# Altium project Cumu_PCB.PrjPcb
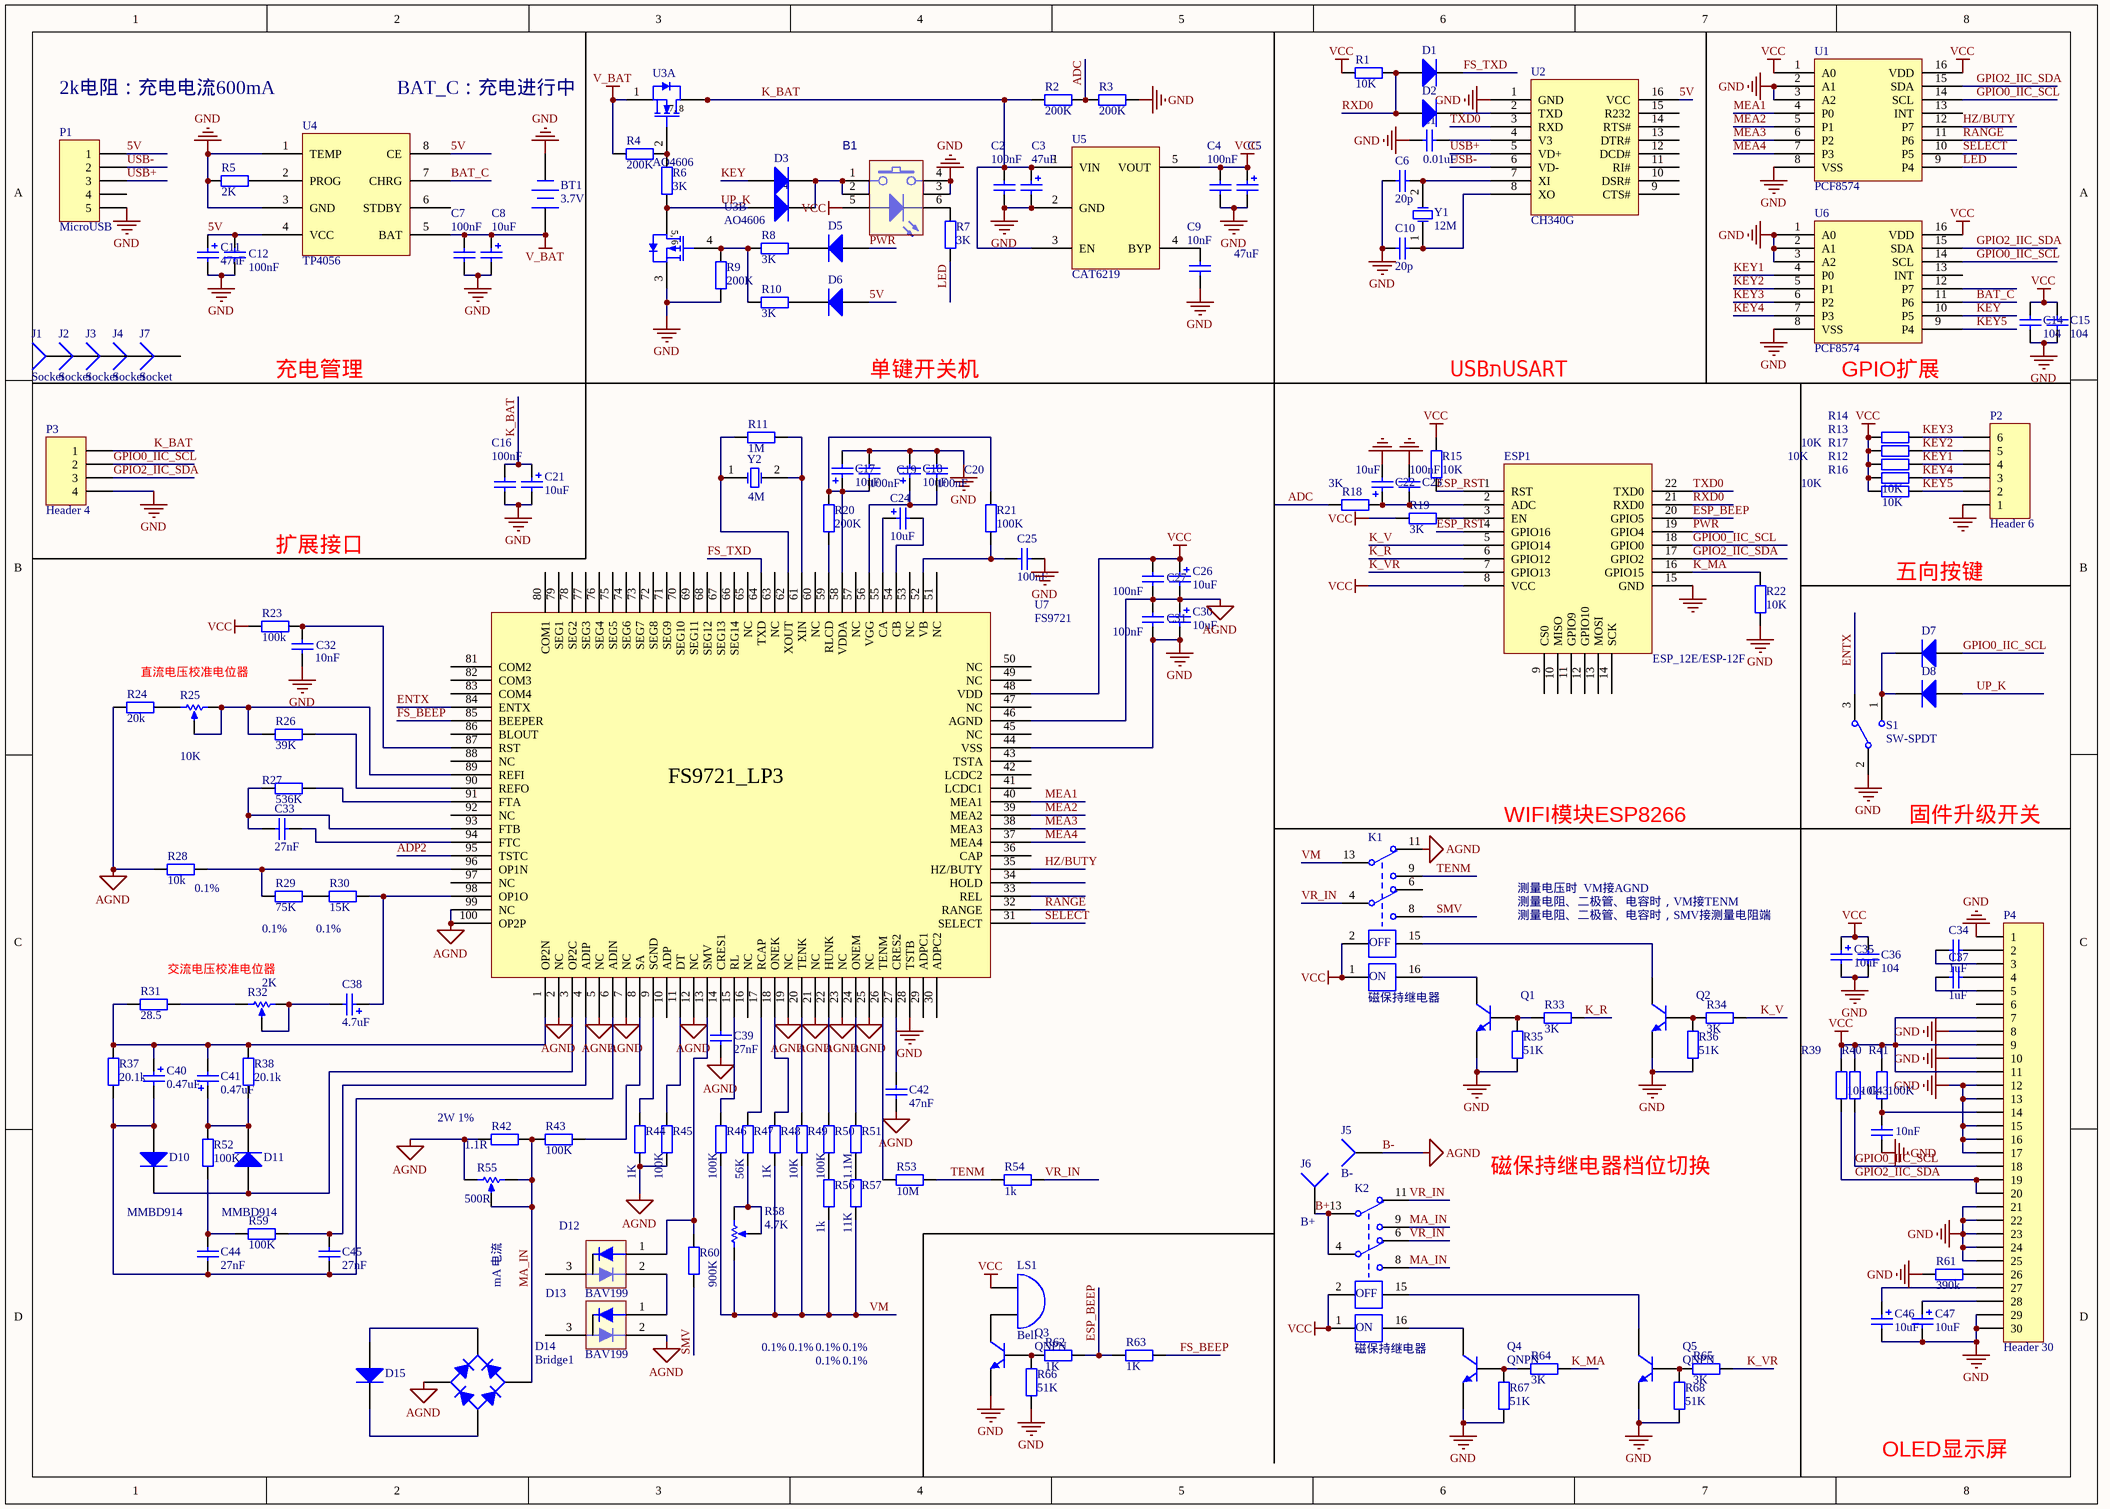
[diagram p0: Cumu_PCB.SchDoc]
1 sheet, 158 parts. Net scope: global (net labels, ports and power ports of the same name join across sheets).
Board file: Cumu_PCB.PcbDoc

## Sheet Cumu_PCB.SchDoc
size A3

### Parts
B1  SW-led  [SW-6-LED]  (value not drawn)
BT1  3.7V  [BAT-2]
C1  value 0.01uF  [0603C]  (hidden comment: Cap)
C2  value 100nF  [0603C]  (hidden comment: Cap)
C3  value 47uF  [SMD-EC-F5]  (hidden comment: Cap Pol2)
C4  value 100nF  [0603C]  (hidden comment: Cap)
C5  value 47uF  [SMD-EC-F5]  (hidden comment: Cap Pol2)
C6  value 20p  [0603C]  (hidden comment: Cap)
C7  value 100nF  [0603C]  (hidden comment: Cap)
C8  value 10uF  [CAP_A]  (hidden comment: Cap Pol2)
C9  value 10nF  [0603C]  (hidden comment: Cap)
C10  value 20p  [0603C]  (hidden comment: Cap)
C11  value 47uF  [SMD-EC-F5]  (hidden comment: Cap Pol2)
C12  value 100nF  [0603C]  (hidden comment: Cap)
C14  value 104  [0603C]  (hidden comment: Cap)
C15  value 104  [0603C]  (hidden comment: Cap)
C16  value 100nF  [0603C]  (hidden comment: Cap)
C17  value 10uF  [CAP_A]  (hidden comment: Cap Pol2)
C18  value 10uF  [CAP_A]  (hidden comment: Cap Pol2)
C19  value 100nF  [0603C]  (hidden comment: Cap)
C20  value 100nF  [0603C]  (hidden comment: Cap)
C21  value 10uF  [CAP_A]  (hidden comment: Cap Pol2)
C22  value 10uF  [CAP_A]  (hidden comment: Cap Pol2)
C23  value 100nF  [0603C]  (hidden comment: Cap)
C24  value 10uF  [CAP_A]  (hidden comment: Cap Pol2)
C25  value 100nF  [0603C]  (hidden comment: Cap)
C26  value 10uF  [CAP_A]  (hidden comment: Cap Pol2)
C27  value 100nF  [0603C]  (hidden comment: Cap)
C30  value 10uF  [CAP_A]  (hidden comment: Cap Pol2)
C31  value 100nF  [0603C]  (hidden comment: Cap)
C32  value 10nF  [0603C]  (hidden comment: Cap)
C33  value 27nF  [0603C]  (hidden comment: Cap)
C34  value 1uF  [0603C]  (hidden comment: Cap)
C35  value 10uF  [CAP_A]  (hidden comment: Cap Pol2)
C36  value 104  [0603C]  (hidden comment: Cap)
C37  value 1uF  [0603C]  (hidden comment: Cap)
C38  value 4.7uF  [CAP_A]  (hidden comment: Cap Pol2)
C39  value 27nF  [0603C]  (hidden comment: Cap)
C40  value 0.47uF  [CAP_A]  (hidden comment: Cap Pol2)
C41  value 0.47uF  [CAP_A]  (hidden comment: Cap Pol2)
C42  value 47nF  [0603C]  (hidden comment: Cap)
C43  value 10nF  [0603C]  (hidden comment: Cap)
C44  value 27nF  [0603C]  (hidden comment: Cap)
C45  value 27nF  [0603C]  (hidden comment: Cap)
C46  value 10uF  [CAP_A]  (hidden comment: Cap Pol2)
C47  value 10uF  [CAP_A]  (hidden comment: Cap Pol2)
D1  MBRA340  [M7 1206]  (value not drawn)
D2  MBRA340  [M7 1206]  (value not drawn)
D3  MBRA340  [M7 1206]  (value not drawn)
D4  MBRA340  [M7 1206]  (value not drawn)
D5  MBRA340  [M7 1206]  (value not drawn)
D6  MBRA340  [M7 1206]  (value not drawn)
D7  MBRA340  [M7 1206]  (value not drawn)
D8  MBRA340  [M7 1206]  (value not drawn)
D10  MMBD914  [SOT-23B]
D11  MMBD914  [SOT-23B]
D12  BAV199  [SOT-23B]
D13  BAV199  [SOT-23B]
D14  Bridge1  [DB107S]
D15  MBRA340  [SMA]  (value not drawn)
ESP1  ESP_12E/ESP-12F  [ESP12_BOT]
J1  Socket  [GDK]
J2  Socket  [GDK]
J3  Socket  [GDK]
J4  Socket  [GDK]
J5  B-  [pen]
J6  B+  [pen]
J7  Socket  [GDK]
K1  磁保持继电器  [HFD2/005-M-L2]
K2  磁保持继电器  [HFD2/005-M-L2]
LS1  Bell  [BUZZ]
P1  MicroUSB  [USB_MICRO -72/66]
P2  Header 6  [5xiang-10*10]
P3  Header 4  [USB_tie]
P4  Header 30  [0,96OLED]
Q1  QNPN  [SOT-23B]  (value not drawn)
Q2  QNPN  [SOT-23B]  (value not drawn)
Q3  QNPN  [SOT-23B]
Q4  QNPN  [SOT-23B]
Q5  QNPN  [SOT-23B]
R1  value 10K  [0603R]  (hidden comment: Res2)
R2  value 200K  [0603R]  (hidden comment: Res2)
R3  value 200K  [0603R]  (hidden comment: Res2)
R4  value 200K  [0603R]  (hidden comment: Res2)
R5  value 2K  [0603R]  (hidden comment: Res2)
R6  value 3K  [0603R]  (hidden comment: Res2)
R7  value 3K  [0603R]  (hidden comment: Res2)
R8  value 3K  [0603R]  (hidden comment: Res2)
R9  value 200K  [0603R]  (hidden comment: Res2)
R10  value 3K  [0603R]  (hidden comment: Res2)
R11  value 1M  [0603R]  (hidden comment: Res2)
R12  value 10K  [0603R]  (hidden comment: Res2)
R13  value 10K  [0603R]  (hidden comment: Res2)
R14  value 10K  [0603R]  (hidden comment: Res2)
R15  value 10K  [0603R]  (hidden comment: Res2)
R16  value 10K  [0603R]  (hidden comment: Res2)
R17  value 10K  [0603R]  (hidden comment: Res2)
R18  value 3K  [0603R]  (hidden comment: Res2)
R19  value 3K  [0603R]  (hidden comment: Res2)
R20  value 200K  [0603R]  (hidden comment: Res2)
R21  value 100K  [0603R]  (hidden comment: Res2)
R22  value 10K  [0603R]  (hidden comment: Res2)
R23  value 100k  [0603R]  (hidden comment: Res2)
R24  value 20k  [0603R]  (hidden comment: Res2)
R25  value 10K  [R3*3]  (hidden comment: RPot)
R26  value 39K  [0603R]  (hidden comment: Res2)
R27  value 536K  [0603R]  (hidden comment: Res2)
R28  value 10k  PackageReference: 0.1%  [0603R]  (hidden comment: Res2)
R29  value 75K  PackageReference: 0.1%  [0603R]  (hidden comment: Res2)
R30  value 15K  PackageReference: 0.1%  [0603R]  (hidden comment: Res2)
R31  value 28.5  [0603R]  (hidden comment: Res2)
R32  value 2K  [R3*3]  (hidden comment: RPot)
R33  value 3K  [0603R]  (hidden comment: Res2)
R34  value 3K  [0603R]  (hidden comment: Res2)
R35  value 51K  [0603R]  (hidden comment: Res2)
R36  value 51K  [0603R]  (hidden comment: Res2)
R37  value 20.1k  [0603R]  (hidden comment: Res2)
R38  value 20.1k  [0603R]  (hidden comment: Res2)
R39  value 10k  [0603R]  (hidden comment: Res2)
R40  value 10k  [0603R]  (hidden comment: Res2)
R41  value 100K  [0603R]  (hidden comment: Res2)
R42  2W 1%  value 1.1R  [AXIAL-0.7]
R43  value 100K  [0603R]  (hidden comment: Res2)
R44  value 1K  [0603R]  (hidden comment: Res2)
R45  value 100K  [0603R]  (hidden comment: Res2)
R46  value 100K  [0603R]  (hidden comment: Res2)
R47  value 56K  [0603R]  (hidden comment: Res2)
R48  value 1K  PackageReference: 0.1%  [0603R]  (hidden comment: Res2)
R49  value 10K  PackageReference: 0.1%  [0603R]  (hidden comment: Res2)
R50  value 100K  PackageReference: 0.1%  [0603R]  (hidden comment: Res2)
R51  value 1.1M  PackageReference: 0.1%  [0603R]  (hidden comment: Res2)
R52  value 100K  [0603R]  (hidden comment: Res2)
R53  value 10M  [0603R]  (hidden comment: Res2)
R54  value 1k  [0603R]
R55  value 500R  [R3*3]  (hidden comment: RPot)
R56  value 1k  PackageReference: 0.1%  [0603R]  (hidden comment: Res2)
R57  value 11K  PackageReference: 0.1%  [0603R]  (hidden comment: Res2)
R58  value 4.7K  [R3*3]  (hidden comment: RPot)
R59  value 100K  [0603R]  (hidden comment: Res2)
R60  value 900K  [0603R]  (hidden comment: Res2)
R61  value 390k  [0603R]  (hidden comment: Res2)
R62  value 1K  [0603R]  (hidden comment: Res2)
R63  value 1K  [0603R]  (hidden comment: Res2)
R64  value 3K  [0603R]  (hidden comment: Res2)
R65  value 3K  [0603R]  (hidden comment: Res2)
R66  value 51K  [0603R]  (hidden comment: Res2)
R67  value 51K  [0603R]  (hidden comment: Res2)
R68  value 51K  [0603R]  (hidden comment: Res2)
S1  SW-SPDT  [SS-12D07]
U1  PCF8574  [SOP-16]
U2  CH340G  [SO-16]
U3  AO4606  [SO-8]  (parts A,B of 2)
U4  TP4056  [SO-8 - 9]
U5  CAT6219  [MA05B]
U6  PCF8574  [SOP-16]
U7  FS9721  [QFP100]
Y1  12M  [HC-49]
Y2  4M  [HC-49]

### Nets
B-: C26.2 C27.1 C30.1 C31.2 C39.2 C42.2 D13.2 D14.4(C) J5.1 K1.11 R24.2 R28.2 R42.2 R44.2 R45.2 R55.1(TOP) U7.2(NC) U7.5(NC) U7.7(NC) U7.12(NC) U7.19(NC) U7.21(NC) U7.23(NC) U7.25(NC) U7.46(AGND) U7.99(NC) U7.100(OP2P)  [also labelled AGND]
GND: B1.3 B1.4 BT1.2(-) C1.2 C2.1 C3.2 C4.1 C5.2 C6.2 C7.1 C8.2 C9.1 C10.2 C11.2 C12.1 C14.2 C15.2 C16.1 C17.2 C18.2 C19.1 C20.1 C21.2 C22.2 C23.1 C25.1 C30.2 C31.1 C32.1 C35.2 C36.2 C43.1 C46.2 C47.2 ESP1.15(GND) P1.5 P2.1 P3.4 P4.1 P4.8 P4.10 P4.12 P4.13 P4.15 P4.16 P4.17 P4.21 P4.22 P4.23 P4.24 P4.25 P4.29 P4.30 Q1.2(E) Q2.2(E) Q3.2(E) Q4.2(E) Q5.2(E) R3.1 R5.1 R9.1 R22.1 R35.1 R36.1 R61.2 R66.1 R67.1 R68.1 S1.2 U1.2(A1) U1.3(A2) U1.8(VSS) U2.1(GND) U3.3(S) U4.1(TEMP) U4.3(GND) U5.2(GND) U6.1(A0) U6.2(A1) U6.3(A2) U6.8(VSS) U7.28(TSTB) U7.44(VSS)
V_BAT: BT1.1(+) C7.2 C8.1 R4.1 U3.1(S) U4.5(BAT)
VCC: B1.5 C4.2 C5.1 C14.1 C15.1 C26.1 C27.2 C35.1 C36.1 ESP1.8(VCC) K1.1(+) K1.2 K2.1(+) K2.2 LS1.2(B) P4.7 P4.9 P4.11 R1.2 R12.2 R13.1 R14.2 R15.2 R16.2 R17.2 R19.1 R23.2 R39.2 R40.2 R41.1 U1.1(A0) U1.16(VDD) U5.5(VOUT) U6.16(VDD) U7.48(VDD)
5V: C11.1 C12.2 D6.1(A) P1.1 U2.16(VCC) U4.4(VCC) U4.8(CE)
ADC: R2.1 R3.2 R18.1
ADP2: U7.95(TSTC)
B+: J6.1 K2.4 K2.13
BAT_C: U4.7(CHRG) U6.11(P6)
ENTX: S1.3 U7.84(ENTX)
ESP_BEEP: ESP1.20(GPIO5) R62.2 R63.1
ESP_RST: ESP1.1(RST) ESP1.4(GPIO16) R15.1
FS_BEEP: R63.2 U7.85(BEEPER)
FS_TXD: D1.2(K) U7.64(TXD)
GPIO0_IIC_SCL: D7.1(A) ESP1.18(GPIO0) P3.2 P4.18 R40.1 U1.14(SCL) U6.14(SCL)
GPIO2_IIC_SDA: ESP1.17(GPIO2) P3.3 P4.19 P4.20 R39.1 U1.15(SDA) U6.15(SDA)
HZ/BUTY: U1.12(P7) U7.35(HZ/BUTY)
K_BAT: C2.2 C3.1 C16.2 C21.1 P3.1 R2.2 U3.7(D) U3.8(D) U5.1(VIN) U5.3(EN)
K_MA: ESP1.16(GPIO15) R22.2 R64.2
K_R: ESP1.6(GPIO12) R33.2
K_V: ESP1.5(GPIO14) R34.2
K_VR: ESP1.7(GPIO13) R65.2
KEY: D3.1(A) U6.10(P5)
KEY1: P2.4 R12.1 U6.4(P0)
KEY2: P2.5 R13.2 U6.5(P1)
KEY3: P2.6 R14.1 U6.6(P2)
KEY4: P2.3 R16.1 U6.7(P3)
KEY5: P2.2 R17.1 U6.9(P4)
LED: R7.2 U1.9(P4)
MA_IN: D14.2(C) K2.8 K2.9 R42.1 R43.2 R55.2(BOT) R55.3(TAP)
MEA1: U1.4(P0) U7.40(MEA1)
MEA2: U1.5(P1) U7.39(MEA2)
MEA3: U1.6(P2) U7.38(MEA3)
MEA4: U1.7(P3) U7.37(MEA4)
PWR: D5.1(A) ESP1.19(GPIO4)
RANGE: U1.11(P6) U7.32(RANGE)
RXD0: D1.1(A) D2.1(A) ESP1.21(RXD0) R1.1
SELECT: U1.10(P5) U7.31(SELECT)
SMV: K1.8 R60.2
TENM: K1.9 R53.2 R54.1
TXD0: ESP1.22(TXD0) U2.3(RXD)
UP_K: D4.1(A) D8.1(A) R6.1 U3.5(D) U3.6(D)
USB+: P1.3 U2.5(VD+)
USB-: P1.2 U2.6(VD-)
VM: K1.13 R46.2 R48.2 R49.2 R56.2 R57.2 R58.1(TOP)
VR_IN: K1.4 K2.6 K2.11 R54.2
NetB1_1: B1.1 B1.2 D3.2(K) D4.2(K)
NetB1_6: B1.6 R7.1
NetC1_1: C1.1 U2.4(V3)
NetC6_1: C6.1 U2.7(XI) Y1.2(OSC2)
NetC9_2: C9.2 U5.4(BYP)
NetC10_1: C10.1 U2.8(XO) Y1.1(OSC1)
NetC17_1: C17.1 C19.2 R20.1 R21.1 U7.58(VDDA)
NetC18_1: C18.1 C20.2 U7.56(VGG)
NetC22_1: C22.1 C23.2 ESP1.2(ADC) R18.2
NetC24_1: C24.1 U7.55(CA)
NetC24_2: C24.2 U7.54(CB)
NetC25_2: C25.2 R21.2 U7.52(VB)
NetC32_2: C32.2 R23.1 U7.87(RST)
NetC33_1: C33.1 U7.94(FTC)
NetC33_2: C33.2 R27.2 U7.93(FTB)
NetC34_1: C34.1 P4.3
NetC34_2: C34.2 P4.2
NetC37_1: C37.1 P4.5
NetC37_2: C37.2 P4.4
NetC38_1: C38.1 R30.1 U7.98(OP1O)
NetC38_2: C38.2 R32.2(BOT) R32.3(TAP)
NetC39_1: C39.1 U7.14(CRES1)
NetC40_1: C40.1 C41.2 R31.2 R37.1 R38.1 U7.1(OP2N)
NetC40_2: C40.2 C44.2 C45.2 D10.1(A) R37.2 U7.6(ADIN)
NetC41_1: C41.1 D11.2(K) R38.2 R52.1
NetC42_1: C42.1 U7.27(CRES2)
NetC43_2: C43.2 P4.14 R41.2
NetC44_1: C44.1 R52.2 R59.1
NetC45_1: C45.1 R59.2 U7.4(ADIP)
NetC46_1: C46.1 P4.27
NetC47_1: C47.1 P4.28
NetD2_2: D2.2(K) U2.2(TXD)
NetD5_2: D5.2(K) R8.1
NetD6_2: D6.2(K) R10.1
NetD7_2: D7.2(K) D8.2(K) S1.1
NetD10_2: D10.2(K) D11.1(A) U7.3(OP2C)
NetD12_1: D12.1 R60.1 U7.13(SMV)
NetD12_2: D12.2 D13.1
NetD14_1: D14.1(K) D15.1(A)
NetD14_3: D14.3(A) D15.2(K)
NetESP1_3: ESP1.3(EN) R19.2
NetK1_15: K1.15 Q2.3(C)
NetK1_16: K1.16 Q1.3(C)
NetK2_15: K2.15 Q5.3(C)
NetK2_16: K2.16 Q4.3(C)
NetLS1_1: LS1.1(A) Q3.3(C)
NetP4_26: P4.26 R61.1
NetQ1_1: Q1.1(B) R33.1 R35.2
NetQ2_1: Q2.1(B) R34.1 R36.2
NetQ3_1: Q3.1(B) R62.1 R66.2
NetQ4_1: Q4.1(B) R64.1 R67.2
NetQ5_1: Q5.1(B) R65.1 R68.2
NetR4_2: R4.2 R6.2 U3.2(G)
NetR5_2: R5.2 U4.2(PROG)
NetR8_2: R8.2 R9.2 R10.2 U3.4(G)
NetR11_1: R11.1 U7.61(XIN) Y2.2(OSC2)
NetR11_2: R11.2 U7.62(XOUT) Y2.1(OSC1)
NetR20_2: R20.2 U7.59(RLCD)
NetR24_1: R24.1 R25.1(TOP)
NetR25_2: R25.2(BOT) R25.3(TAP) R26.2 U7.89(REFI)
NetR26_1: R26.1 U7.90(REFO)
NetR27_1: R27.1 U7.91(FTA)
NetR28_1: R28.1 R29.2 U7.96(OP1N)
NetR29_1: R29.1 R30.2
NetR31_1: R31.1 R32.1(TOP)
NetR43_1: R43.1 U7.8(SA)
NetR44_1: R44.1 U7.9(SGND)
NetR45_1: R45.1 U7.11(DT)
NetR46_1: R46.1 U7.15(RL)
NetR47_1: R47.1 U7.17(RCAP)
NetR47_2: R47.2 R58.2(BOT) R58.3(TAP)
NetR48_1: R48.1 U7.18(ONEK)
NetR49_1: R49.1 U7.20(TENK)
NetR50_1: R50.1 U7.22(HUNK)
NetR50_2: R50.2 R56.1
NetR51_1: R51.1 U7.24(ONEM)
NetR51_2: R51.2 R57.1
NetR53_1: R53.1 U7.26(TENM)

Not connected (* = marked no-connect by the designer): D12 3; D13 3; ESP1 9(CS0) 10(MISO) 11(GPIO9) 12(GPIO10) 13(MOSI) 14(SCK); J1 1; J2 1; J3 1; J4 1; J7 1; K1 6; P1 4; P4 6; U1 13(INT); U2 9(CTS#) 10(DSR#) 11(RI#) 12(DCD#) 13(DTR#) 14(RTS#) 15(R232); U4 6(STDBY); U6 12(P7) 13(INT); U7 10(ADP) 16(NC) 29(ADPC1) 30(ADPC2) 33(REL) 34(HOLD) 36(CAP) 41(LCDC1) 42(LCDC2) 43(TSTA) 45(NC) 47(NC) 49(NC) 50(NC) 51(NC) 53(NC) 57(NC) 60(NC) 63(NC) 65(NC) 66(SEG14) 67(SEG13) 68(SEG12) 69(SEG11) 70(SEG10) 71(SEG9) 72(SEG8) 73(SEG7) 74(SEG6) 75(SEG5) 76(SEG4) 77(SEG3) 78(SEG2) 79(SEG1) 80(COM1) 81(COM2) 82(COM3) 83(COM4) 86(BLOUT) 88(NC) 92(NC) 97(NC)

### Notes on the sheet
- 2k电阻：充电电流600mA
- BAT_C：充电进行中
- 充电管理
- 单键开关机
- USBתUSART
- (near U6) GPIO扩展
- 扩展接口
- 五向按键
- 直流电压校准电位器
- WIFI模块ESP8266
- 固件升级开关
- 测量电压时  VM接AGND
- 测量电阻、二极管、电容时，VM接TENM
- 测量电阻、二极管、电容时，SMV接测量电阻端
- 交流电压校准电位器
- 磁保持继电器档位切换
- mA 电流
- OLED显示屏

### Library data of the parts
B1 = SW-led: Manuf_Part_1: TD-0341; Ref St: ********; cap_dec: ---; Description: Non-Open Push-Button 0.1A 24V
BT1 = Battery: Multicell Battery
C1 C2 C4 C6 C7 C9 C10 C12 C14-C16 C19 C20 C23 C25 C27 C31-C34 C36 C37 C39 C42-C45 = Cap: Capacitor
C3 C5 C8 C11 C17 C18 C21 C22 C24 C26 C30 C35 C38 C40 C41 C46 C47 = Cap Pol2: Polarized Capacitor (Axial)
D1-D8 D15 = Diode 1N5408: 3 Amp Medium Power Silicon Rectifier Diode
D10 D11 = Diode 1N5408: 3 Amp Medium Power Silicon Rectifier Diode; pin to pad: 2>3
D14 = Bridge1: Full Wave Diode Bridge
ESP1 = ESP_12
J5 J6 = Socket
K1 K2 = HFD2/005-M-L2
LS1 = Bell: Electrical Bell
P1 = Header 5: Header, 5-Pin
P2 = Header 6: Header, 6-Pin
P3 = Header 4: Header, 4-Pin
P4 = Header 30: Header, 30-Pin
Q1-Q5 = QNPN: NPN Bipolar Transistor
R1-R24 R26-R31 R33-R54 R56 R57 R59-R68 = Res2: Resistor
R25 R32 R55 R58 = RPot: Potentiometer; Sim Note: Enter the Resistance value and the set point into parameter fields.; Set Position: 0.5
S1 = SW-SPDT: SPDT Subminiature Toggle Switch, Right Angle Mounting, Vertical Actuation
U3 = AO4606: Dual P-Channel 2.5V (G-S) Rated  MOSFET
U5 = PM3101
U7 = Component_1
Y1 Y2 = XTAL: Crystal Oscillator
